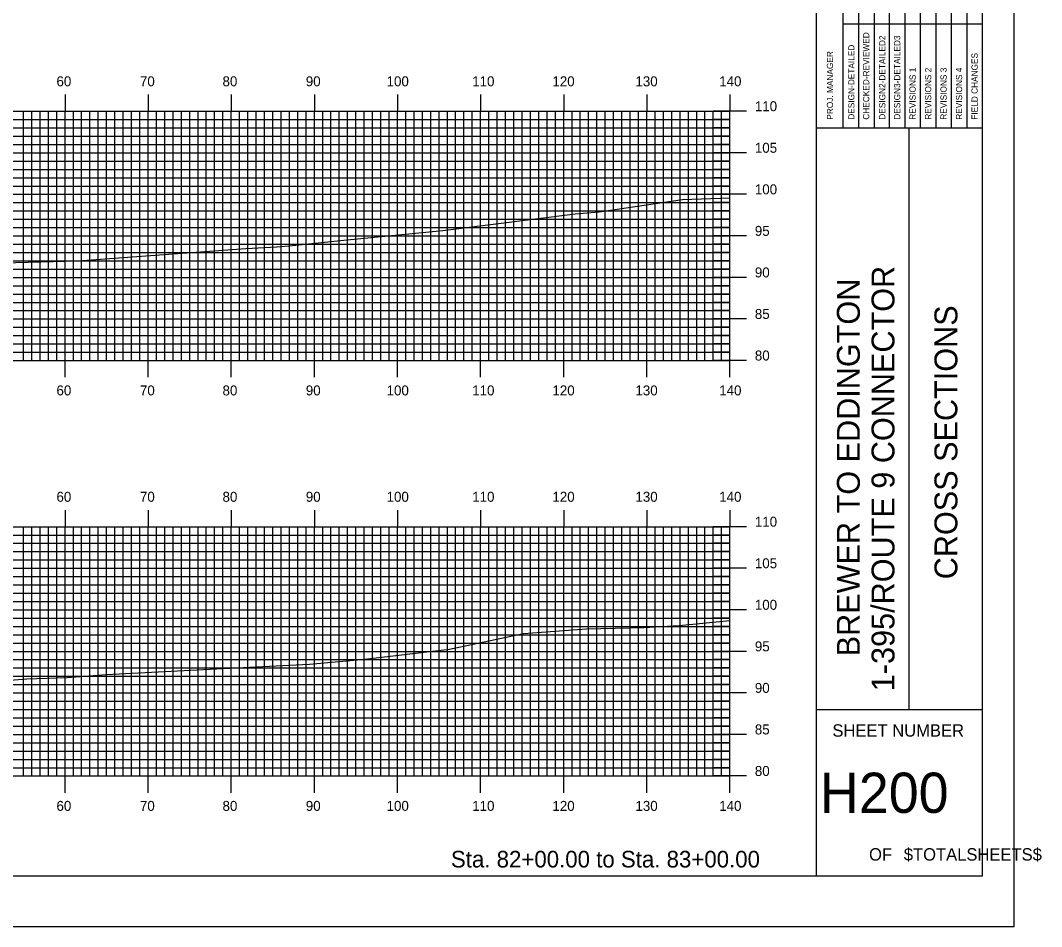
# Model space of a CAD drawing. Extents: x 1762972 to 1763315, y 442591 to 442811.
# Drawn here: x 1763191.9 to 1763314.8, y 442590.5 to 442699.6 of the extents above; entities that cross this region are included whole.
import ezdxf

# ---------------------------------------------------------------- set-up
doc = ezdxf.new("R2010")
doc.units = 0
for name, color, linetype in [('BORDER', 7, 'Continuous'), ('H_V ANNOTATION', 7, 'Continuous'), ('MAJOR', 7, 'Continuous'), ('MINOR', 7, 'Continuous'), ('PLOT BOUNDARY', 7, 'Continuous'), ('S_Roadway_Centerline', 7, 'Continuous')]:
    doc.layers.add(name, color=color, linetype=linetype)

msp = doc.modelspace()

# ---------------------------------------------------------------- linework, layer by layer
at = {"layer": 'BORDER'}
for p, q in [((1763287.69, 442596.67), (1763287.69, 442806.67)), ((1763287.69, 442686.67), (1763307.69, 442686.67)), ((1763298.87, 442616.67), (1763298.87, 442686.67)), ((1763287.69, 442616.67), (1763307.69, 442616.67))]:
    msp.add_line(p, q, dxfattribs=at)
msp.add_lwpolyline([(1762987.69, 442596.67), (1763307.69, 442596.67), (1763307.69, 442806.67), (1762987.69, 442806.67)], close=True, dxfattribs=at)
for points in [[(1763292.79, 442686.68), (1763292.79, 442721.67)], [(1763294.65, 442721.67), (1763294.65, 442686.68)], [(1763296.51, 442686.68), (1763296.51, 442721.67)], [(1763298.38, 442686.68), (1763298.38, 442721.67)], [(1763300.24, 442686.68), (1763300.24, 442721.67)], [(1763302.1, 442686.68), (1763302.1, 442721.67)], [(1763303.97, 442686.68), (1763303.97, 442721.67)], [(1763305.83, 442686.68), (1763305.83, 442721.67)], [(1763290.92, 442686.68), (1763290.92, 442720.26)], [(1763290.92, 442699.17), (1763307.69, 442699.17)]]:
    msp.add_lwpolyline(points, dxfattribs=at)
at = {"layer": 'MAJOR'}
for p, q in [((1763197.29, 442690.67), (1763197.29, 442688.67)), ((1763207.29, 442690.67), (1763207.29, 442688.67)), ((1763217.29, 442690.67), (1763217.29, 442688.67)), ((1763227.29, 442690.67), (1763227.29, 442688.67)), ((1763237.29, 442690.67), (1763237.29, 442688.67)), ((1763247.29, 442690.67), (1763247.29, 442688.67)), ((1763257.29, 442690.67), (1763257.29, 442688.67)), ((1763267.29, 442690.67), (1763267.29, 442688.67)), ((1763277.29, 442690.67), (1763277.29, 442688.67)), ((1762997.29, 442688.67), (1763277.29, 442688.67)), ((1762997.29, 442688.67), (1763277.29, 442688.67)), ((1763197.29, 442658.67), (1763197.29, 442688.67)), ((1763207.29, 442658.67), (1763207.29, 442688.67)), ((1763217.29, 442658.67), (1763217.29, 442688.67)), ((1763227.29, 442658.67), (1763227.29, 442688.67)), ((1763237.29, 442658.67), (1763237.29, 442688.67)), ((1763247.29, 442658.67), (1763247.29, 442688.67)), ((1763257.29, 442658.67), (1763257.29, 442688.67)), ((1763267.29, 442658.67), (1763267.29, 442688.67)), ((1763279.3, 442688.67), (1763275.29, 442688.67)), ((1763277.29, 442658.67), (1763277.29, 442688.67)), ((1763277.29, 442658.67), (1763277.29, 442688.67)), ((1762997.29, 442683.67), (1763277.29, 442683.67)), ((1763279.3, 442683.67), (1763275.29, 442683.67)), ((1762997.29, 442678.67), (1763277.29, 442678.67)), ((1763279.3, 442678.67), (1763275.29, 442678.67)), ((1762997.29, 442673.67), (1763277.29, 442673.67)), ((1763279.3, 442673.67), (1763275.29, 442673.67)), ((1762997.29, 442668.67), (1763277.29, 442668.67)), ((1763279.3, 442668.67), (1763275.29, 442668.67)), ((1762997.29, 442663.67), (1763277.29, 442663.67)), ((1763279.3, 442663.67), (1763275.29, 442663.67)), ((1762997.29, 442658.67), (1763277.29, 442658.67)), ((1762997.29, 442658.67), (1763277.29, 442658.67)), ((1763197.29, 442656.66), (1763197.29, 442658.67)), ((1763207.29, 442656.66), (1763207.29, 442658.67)), ((1763217.29, 442656.66), (1763217.29, 442658.67)), ((1763227.29, 442656.66), (1763227.29, 442658.67)), ((1763237.29, 442656.66), (1763237.29, 442658.67)), ((1763247.29, 442656.66), (1763247.29, 442658.67)), ((1763257.29, 442656.66), (1763257.29, 442658.67)), ((1763267.29, 442656.66), (1763267.29, 442658.67)), ((1763279.3, 442658.67), (1763275.29, 442658.67)), ((1763277.29, 442656.66), (1763277.29, 442658.67)), ((1763197.29, 442640.67), (1763197.29, 442638.67)), ((1763207.29, 442640.67), (1763207.29, 442638.67)), ((1763217.29, 442640.67), (1763217.29, 442638.67)), ((1763227.29, 442640.67), (1763227.29, 442638.67)), ((1763237.29, 442640.67), (1763237.29, 442638.67)), ((1763247.29, 442640.67), (1763247.29, 442638.67)), ((1763257.29, 442640.67), (1763257.29, 442638.67)), ((1763267.29, 442640.67), (1763267.29, 442638.67)), ((1763277.29, 442640.67), (1763277.29, 442638.67)), ((1762997.29, 442638.67), (1763277.29, 442638.67)), ((1762997.29, 442638.67), (1763277.29, 442638.67)), ((1763197.29, 442608.67), (1763197.29, 442638.67)), ((1763207.29, 442608.67), (1763207.29, 442638.67)), ((1763217.29, 442608.67), (1763217.29, 442638.67)), ((1763227.29, 442608.67), (1763227.29, 442638.67)), ((1763237.29, 442608.67), (1763237.29, 442638.67)), ((1763247.29, 442608.67), (1763247.29, 442638.67)), ((1763257.29, 442608.67), (1763257.29, 442638.67)), ((1763267.29, 442608.67), (1763267.29, 442638.67)), ((1763279.3, 442638.67), (1763275.29, 442638.67)), ((1763277.29, 442608.67), (1763277.29, 442638.67)), ((1763277.29, 442608.67), (1763277.29, 442638.67)), ((1762997.29, 442633.67), (1763277.29, 442633.67)), ((1763279.3, 442633.67), (1763275.29, 442633.67)), ((1762997.29, 442628.67), (1763277.29, 442628.67)), ((1763279.3, 442628.67), (1763275.29, 442628.67)), ((1762997.29, 442623.67), (1763277.29, 442623.67)), ((1763279.3, 442623.67), (1763275.29, 442623.67)), ((1762997.29, 442618.67), (1763277.29, 442618.67)), ((1763279.3, 442618.67), (1763275.29, 442618.67)), ((1762997.29, 442613.67), (1763277.29, 442613.67)), ((1763279.3, 442613.67), (1763275.29, 442613.67)), ((1762997.29, 442608.67), (1763277.29, 442608.67)), ((1762997.29, 442608.67), (1763277.29, 442608.67)), ((1763197.29, 442606.66), (1763197.29, 442608.67)), ((1763207.29, 442606.66), (1763207.29, 442608.67)), ((1763217.29, 442606.66), (1763217.29, 442608.67)), ((1763227.29, 442606.66), (1763227.29, 442608.67)), ((1763237.29, 442606.66), (1763237.29, 442608.67)), ((1763247.29, 442606.66), (1763247.29, 442608.67)), ((1763257.29, 442606.66), (1763257.29, 442608.67)), ((1763267.29, 442606.66), (1763267.29, 442608.67)), ((1763279.3, 442608.67), (1763275.29, 442608.67)), ((1763277.29, 442606.66), (1763277.29, 442608.67))]:
    msp.add_line(p, q, dxfattribs=at)
at = {"layer": 'MINOR'}
for p, q in [((1763192.29, 442658.67), (1763192.29, 442688.67)), ((1763193.29, 442658.67), (1763193.29, 442688.67)), ((1763194.29, 442658.67), (1763194.29, 442688.67)), ((1763195.29, 442658.67), (1763195.29, 442688.67)), ((1763196.29, 442658.67), (1763196.29, 442688.67)), ((1763198.29, 442658.67), (1763198.29, 442688.67)), ((1763199.29, 442658.67), (1763199.29, 442688.67)), ((1763200.29, 442658.67), (1763200.29, 442688.67)), ((1763201.29, 442658.67), (1763201.29, 442688.67)), ((1763202.29, 442658.67), (1763202.29, 442688.67)), ((1763203.29, 442658.67), (1763203.29, 442688.67)), ((1763204.29, 442658.67), (1763204.29, 442688.67)), ((1763205.29, 442658.67), (1763205.29, 442688.67)), ((1763206.29, 442658.67), (1763206.29, 442688.67)), ((1763208.29, 442658.67), (1763208.29, 442688.67)), ((1763209.29, 442658.67), (1763209.29, 442688.67)), ((1763210.29, 442658.67), (1763210.29, 442688.67)), ((1763211.29, 442658.67), (1763211.29, 442688.67)), ((1763212.29, 442658.67), (1763212.29, 442688.67)), ((1763213.29, 442658.67), (1763213.29, 442688.67)), ((1763214.29, 442658.67), (1763214.29, 442688.67)), ((1763215.29, 442658.67), (1763215.29, 442688.67)), ((1763216.29, 442658.67), (1763216.29, 442688.67)), ((1763218.29, 442658.67), (1763218.29, 442688.67)), ((1763219.29, 442658.67), (1763219.29, 442688.67)), ((1763220.29, 442658.67), (1763220.29, 442688.67)), ((1763221.29, 442658.67), (1763221.29, 442688.67)), ((1763222.29, 442658.67), (1763222.29, 442688.67)), ((1763223.29, 442658.67), (1763223.29, 442688.67)), ((1763224.29, 442658.67), (1763224.29, 442688.67)), ((1763225.29, 442658.67), (1763225.29, 442688.67)), ((1763226.29, 442658.67), (1763226.29, 442688.67)), ((1763228.29, 442658.67), (1763228.29, 442688.67)), ((1763229.29, 442658.67), (1763229.29, 442688.67)), ((1763230.29, 442658.67), (1763230.29, 442688.67)), ((1763231.29, 442658.67), (1763231.29, 442688.67)), ((1763232.29, 442658.67), (1763232.29, 442688.67)), ((1763233.29, 442658.67), (1763233.29, 442688.67)), ((1763234.29, 442658.67), (1763234.29, 442688.67)), ((1763235.29, 442658.67), (1763235.29, 442688.67)), ((1763236.29, 442658.67), (1763236.29, 442688.67)), ((1763238.29, 442658.67), (1763238.29, 442688.67)), ((1763239.29, 442658.67), (1763239.29, 442688.67)), ((1763240.29, 442658.67), (1763240.29, 442688.67)), ((1763241.29, 442658.67), (1763241.29, 442688.67)), ((1763242.29, 442658.67), (1763242.29, 442688.67)), ((1763243.29, 442658.67), (1763243.29, 442688.67)), ((1763244.29, 442658.67), (1763244.29, 442688.67)), ((1763245.29, 442658.67), (1763245.29, 442688.67)), ((1763246.29, 442658.67), (1763246.29, 442688.67)), ((1763248.29, 442658.67), (1763248.29, 442688.67)), ((1763249.29, 442658.67), (1763249.29, 442688.67)), ((1763250.29, 442658.67), (1763250.29, 442688.67)), ((1763251.29, 442658.67), (1763251.29, 442688.67)), ((1763252.29, 442658.67), (1763252.29, 442688.67)), ((1763253.29, 442658.67), (1763253.29, 442688.67)), ((1763254.29, 442658.67), (1763254.29, 442688.67)), ((1763255.29, 442658.67), (1763255.29, 442688.67)), ((1763256.29, 442658.67), (1763256.29, 442688.67)), ((1763258.29, 442658.67), (1763258.29, 442688.67)), ((1763259.29, 442658.67), (1763259.29, 442688.67)), ((1763260.29, 442658.67), (1763260.29, 442688.67)), ((1763261.29, 442658.67), (1763261.29, 442688.67)), ((1763262.29, 442658.67), (1763262.29, 442688.67)), ((1763263.29, 442658.67), (1763263.29, 442688.67)), ((1763264.29, 442658.67), (1763264.29, 442688.67)), ((1763265.29, 442658.67), (1763265.29, 442688.67)), ((1763266.29, 442658.67), (1763266.29, 442688.67)), ((1763268.29, 442658.67), (1763268.29, 442688.67)), ((1763269.29, 442658.67), (1763269.29, 442688.67)), ((1763270.29, 442658.67), (1763270.29, 442688.67)), ((1763271.29, 442658.67), (1763271.29, 442688.67)), ((1763272.29, 442658.67), (1763272.29, 442688.67)), ((1763273.29, 442658.67), (1763273.29, 442688.67)), ((1763274.29, 442658.67), (1763274.29, 442688.67)), ((1763275.29, 442658.67), (1763275.29, 442688.67)), ((1763276.29, 442658.67), (1763276.29, 442688.67)), ((1762997.29, 442687.67), (1763277.29, 442687.67)), ((1763277.29, 442687.67), (1763275.29, 442687.67)), ((1762997.29, 442686.67), (1763277.29, 442686.67)), ((1763277.29, 442686.67), (1763275.29, 442686.67)), ((1762997.29, 442685.67), (1763277.29, 442685.67)), ((1762997.29, 442684.67), (1763277.29, 442684.67)), ((1763277.29, 442685.67), (1763275.29, 442685.67)), ((1763277.29, 442684.67), (1763275.29, 442684.67)), ((1762997.29, 442682.67), (1763277.29, 442682.67)), ((1763277.29, 442682.67), (1763275.29, 442682.67)), ((1762997.29, 442681.67), (1763277.29, 442681.67)), ((1763277.29, 442681.67), (1763275.29, 442681.67)), ((1762997.29, 442680.67), (1763277.29, 442680.67)), ((1762997.29, 442679.67), (1763277.29, 442679.67)), ((1763277.29, 442680.67), (1763275.29, 442680.67)), ((1763277.29, 442679.67), (1763275.29, 442679.67)), ((1762997.29, 442677.67), (1763277.29, 442677.67)), ((1763277.29, 442677.67), (1763275.29, 442677.67)), ((1762997.29, 442676.67), (1763277.29, 442676.67)), ((1763277.29, 442676.67), (1763275.29, 442676.67)), ((1762997.29, 442675.67), (1763277.29, 442675.67)), ((1763277.29, 442675.67), (1763275.29, 442675.67)), ((1762997.29, 442674.67), (1763277.29, 442674.67)), ((1763277.29, 442674.67), (1763275.29, 442674.67)), ((1762997.29, 442672.67), (1763277.29, 442672.67)), ((1763277.29, 442672.67), (1763275.29, 442672.67)), ((1762997.29, 442671.67), (1763277.29, 442671.67)), ((1763277.29, 442671.67), (1763275.29, 442671.67)), ((1762997.29, 442670.67), (1763277.29, 442670.67)), ((1763277.29, 442670.67), (1763275.29, 442670.67)), ((1762997.29, 442669.67), (1763277.29, 442669.67)), ((1763277.29, 442669.67), (1763275.29, 442669.67)), ((1762997.29, 442667.67), (1763277.29, 442667.67)), ((1763277.29, 442667.67), (1763275.29, 442667.67)), ((1762997.29, 442666.67), (1763277.29, 442666.67)), ((1763277.29, 442666.67), (1763275.29, 442666.67)), ((1762997.29, 442665.67), (1763277.29, 442665.67)), ((1763277.29, 442665.67), (1763275.29, 442665.67)), ((1762997.29, 442664.67), (1763277.29, 442664.67)), ((1763277.29, 442664.67), (1763275.29, 442664.67)), ((1762997.29, 442662.67), (1763277.29, 442662.67)), ((1763277.29, 442662.67), (1763275.29, 442662.67)), ((1762997.29, 442661.67), (1763277.29, 442661.67)), ((1763277.29, 442661.67), (1763275.29, 442661.67)), ((1762997.29, 442660.67), (1763277.29, 442660.67)), ((1763277.29, 442660.67), (1763275.29, 442660.67)), ((1762997.29, 442659.67), (1763277.29, 442659.67)), ((1763277.29, 442659.67), (1763275.29, 442659.67)), ((1763192.29, 442608.67), (1763192.29, 442638.67)), ((1763193.29, 442608.67), (1763193.29, 442638.67)), ((1763194.29, 442608.67), (1763194.29, 442638.67)), ((1763195.29, 442608.67), (1763195.29, 442638.67)), ((1763196.29, 442608.67), (1763196.29, 442638.67)), ((1763198.29, 442608.67), (1763198.29, 442638.67)), ((1763199.29, 442608.67), (1763199.29, 442638.67)), ((1763200.29, 442608.67), (1763200.29, 442638.67)), ((1763201.29, 442608.67), (1763201.29, 442638.67)), ((1763202.29, 442608.67), (1763202.29, 442638.67)), ((1763203.29, 442608.67), (1763203.29, 442638.67)), ((1763204.29, 442608.67), (1763204.29, 442638.67)), ((1763205.29, 442608.67), (1763205.29, 442638.67)), ((1763206.29, 442608.67), (1763206.29, 442638.67)), ((1763208.29, 442608.67), (1763208.29, 442638.67)), ((1763209.29, 442608.67), (1763209.29, 442638.67)), ((1763210.29, 442608.67), (1763210.29, 442638.67)), ((1763211.29, 442608.67), (1763211.29, 442638.67)), ((1763212.29, 442608.67), (1763212.29, 442638.67)), ((1763213.29, 442608.67), (1763213.29, 442638.67)), ((1763214.29, 442608.67), (1763214.29, 442638.67)), ((1763215.29, 442608.67), (1763215.29, 442638.67)), ((1763216.29, 442608.67), (1763216.29, 442638.67)), ((1763218.29, 442608.67), (1763218.29, 442638.67)), ((1763219.29, 442608.67), (1763219.29, 442638.67)), ((1763220.29, 442608.67), (1763220.29, 442638.67)), ((1763221.29, 442608.67), (1763221.29, 442638.67)), ((1763222.29, 442608.67), (1763222.29, 442638.67)), ((1763223.29, 442608.67), (1763223.29, 442638.67)), ((1763224.29, 442608.67), (1763224.29, 442638.67)), ((1763225.29, 442608.67), (1763225.29, 442638.67)), ((1763226.29, 442608.67), (1763226.29, 442638.67)), ((1763228.29, 442608.67), (1763228.29, 442638.67)), ((1763229.29, 442608.67), (1763229.29, 442638.67)), ((1763230.29, 442608.67), (1763230.29, 442638.67)), ((1763231.29, 442608.67), (1763231.29, 442638.67)), ((1763232.29, 442608.67), (1763232.29, 442638.67)), ((1763233.29, 442608.67), (1763233.29, 442638.67)), ((1763234.29, 442608.67), (1763234.29, 442638.67)), ((1763235.29, 442608.67), (1763235.29, 442638.67)), ((1763236.29, 442608.67), (1763236.29, 442638.67)), ((1763238.29, 442608.67), (1763238.29, 442638.67)), ((1763239.29, 442608.67), (1763239.29, 442638.67)), ((1763240.29, 442608.67), (1763240.29, 442638.67)), ((1763241.29, 442608.67), (1763241.29, 442638.67)), ((1763242.29, 442608.67), (1763242.29, 442638.67)), ((1763243.29, 442608.67), (1763243.29, 442638.67)), ((1763244.29, 442608.67), (1763244.29, 442638.67)), ((1763245.29, 442608.67), (1763245.29, 442638.67)), ((1763246.29, 442608.67), (1763246.29, 442638.67)), ((1763248.29, 442608.67), (1763248.29, 442638.67)), ((1763249.29, 442608.67), (1763249.29, 442638.67)), ((1763250.29, 442608.67), (1763250.29, 442638.67)), ((1763251.29, 442608.67), (1763251.29, 442638.67)), ((1763252.29, 442608.67), (1763252.29, 442638.67)), ((1763253.29, 442608.67), (1763253.29, 442638.67)), ((1763254.29, 442608.67), (1763254.29, 442638.67)), ((1763255.29, 442608.67), (1763255.29, 442638.67)), ((1763256.29, 442608.67), (1763256.29, 442638.67)), ((1763258.29, 442608.67), (1763258.29, 442638.67)), ((1763259.29, 442608.67), (1763259.29, 442638.67)), ((1763260.29, 442608.67), (1763260.29, 442638.67)), ((1763261.29, 442608.67), (1763261.29, 442638.67)), ((1763262.29, 442608.67), (1763262.29, 442638.67)), ((1763263.29, 442608.67), (1763263.29, 442638.67)), ((1763264.29, 442608.67), (1763264.29, 442638.67)), ((1763265.29, 442608.67), (1763265.29, 442638.67)), ((1763266.29, 442608.67), (1763266.29, 442638.67)), ((1763268.29, 442608.67), (1763268.29, 442638.67)), ((1763269.29, 442608.67), (1763269.29, 442638.67)), ((1763270.29, 442608.67), (1763270.29, 442638.67)), ((1763271.29, 442608.67), (1763271.29, 442638.67)), ((1763272.29, 442608.67), (1763272.29, 442638.67)), ((1763273.29, 442608.67), (1763273.29, 442638.67)), ((1763274.29, 442608.67), (1763274.29, 442638.67)), ((1763275.29, 442608.67), (1763275.29, 442638.67)), ((1763276.29, 442608.67), (1763276.29, 442638.67)), ((1762997.29, 442637.67), (1763277.29, 442637.67)), ((1762997.29, 442636.67), (1763277.29, 442636.67)), ((1763277.29, 442637.67), (1763275.29, 442637.67)), ((1763277.29, 442636.67), (1763275.29, 442636.67)), ((1762997.29, 442635.67), (1763277.29, 442635.67)), ((1763277.29, 442635.67), (1763275.29, 442635.67)), ((1762997.29, 442634.67), (1763277.29, 442634.67)), ((1763277.29, 442634.67), (1763275.29, 442634.67)), ((1762997.29, 442632.67), (1763277.29, 442632.67)), ((1763277.29, 442632.67), (1763275.29, 442632.67)), ((1762997.29, 442631.67), (1763277.29, 442631.67)), ((1762997.29, 442630.67), (1763277.29, 442630.67)), ((1763277.29, 442631.67), (1763275.29, 442631.67)), ((1763277.29, 442630.67), (1763275.29, 442630.67)), ((1762997.29, 442629.67), (1763277.29, 442629.67)), ((1763277.29, 442629.67), (1763275.29, 442629.67)), ((1762997.29, 442627.67), (1763277.29, 442627.67)), ((1763277.29, 442627.67), (1763275.29, 442627.67)), ((1762997.29, 442626.67), (1763277.29, 442626.67)), ((1762997.29, 442625.67), (1763277.29, 442625.67)), ((1763277.29, 442626.67), (1763275.29, 442626.67)), ((1763277.29, 442625.67), (1763275.29, 442625.67)), ((1762997.29, 442624.67), (1763277.29, 442624.67)), ((1763277.29, 442624.67), (1763275.29, 442624.67)), ((1762997.29, 442622.67), (1763277.29, 442622.67)), ((1763277.29, 442622.67), (1763275.29, 442622.67)), ((1762997.29, 442621.67), (1763277.29, 442621.67)), ((1763277.29, 442621.67), (1763275.29, 442621.67)), ((1762997.29, 442620.67), (1763277.29, 442620.67)), ((1762997.29, 442619.67), (1763277.29, 442619.67)), ((1763277.29, 442620.67), (1763275.29, 442620.67)), ((1763277.29, 442619.67), (1763275.29, 442619.67)), ((1762997.29, 442617.67), (1763277.29, 442617.67)), ((1763277.29, 442617.67), (1763275.29, 442617.67)), ((1762997.29, 442616.67), (1763277.29, 442616.67)), ((1763277.29, 442616.67), (1763275.29, 442616.67)), ((1762997.29, 442615.67), (1763277.29, 442615.67)), ((1762997.29, 442614.67), (1763277.29, 442614.67)), ((1763277.29, 442615.67), (1763275.29, 442615.67)), ((1763277.29, 442614.67), (1763275.29, 442614.67)), ((1762997.29, 442612.67), (1763277.29, 442612.67)), ((1763277.29, 442612.67), (1763275.29, 442612.67)), ((1762997.29, 442611.67), (1763277.29, 442611.67)), ((1763277.29, 442611.67), (1763275.29, 442611.67)), ((1762997.29, 442610.67), (1763277.29, 442610.67)), ((1762997.29, 442609.67), (1763277.29, 442609.67)), ((1763277.29, 442610.67), (1763275.29, 442610.67)), ((1763277.29, 442609.67), (1763275.29, 442609.67))]:
    msp.add_line(p, q, dxfattribs=at)
at = {"layer": 'PLOT BOUNDARY'}
msp.add_lwpolyline([(1762971.51, 442590.55), (1763311.51, 442590.55), (1763311.51, 442810.55), (1762971.51, 442810.55)], close=True, dxfattribs=at)
at = {"layer": 'S_Roadway_Centerline'}
for points in [[(1763188.37, 442670.4), (1763198.83, 442670.65), (1763219.06, 442672.15), (1763222.79, 442672.35), (1763224.64, 442672.51), (1763230.83, 442673.15), (1763242.75, 442674.31), (1763253.91, 442675.7), (1763258.66, 442676.34), (1763261.54, 442676.55), (1763271.58, 442678.06), (1763277.29, 442678.23)], [(1763184.04, 442619.67), (1763192.69, 442620.38), (1763197.53, 442620.54), (1763202.22, 442620.9), (1763215.51, 442621.56), (1763226.72, 442622.14), (1763233.36, 442622.73), (1763243.55, 442623.95), (1763252.44, 442625.8), (1763260.03, 442626.36), (1763266.93, 442626.52), (1763271.18, 442626.76), (1763277.29, 442627.39)]]:
    msp.add_lwpolyline(points, dxfattribs=at)

# ---------------------------------------------------------------- texts
at = {"layer": 'BORDER'}
for s, height, p in [('CHECKED-REVIEWED', 0.7455, (1763294.05, 442687.65)), ('DESIGN2-DETAILED2', 0.7455, (1763295.99, 442687.65)), ('DESIGN3-DETAILED3', 0.7455, (1763297.78, 442687.65)), ('PROJ. MANAGER', 0.7455, (1763289.7, 442687.65)), ('DESIGN-DETAILED', 0.7455, (1763292.27, 442687.65)), ('FIELD CHANGES', 0.7455, (1763307.1, 442687.65)), ('REVISIONS 1', 0.7455, (1763299.64, 442687.65)), ('REVISIONS 2', 0.7455, (1763301.51, 442687.65)), ('REVISIONS 3', 0.7455, (1763303.37, 442687.65)), ('REVISIONS 4', 0.7455, (1763305.23, 442687.65)), ('1-395/ROUTE 9 CONNECTOR', 2.7557, (1763297.09, 442618.87)), ('BREWER TO EDDINGTON', 2.7557, (1763292.92, 442623.07)), ('CROSS SECTIONS', 2.7557, (1763304.66, 442632.34))]:
    msp.add_text(s, height=height, rotation=90, dxfattribs=at).set_placement(p)
for s, height, p in [('SHEET NUMBER', 1.4905, (1763289.62, 442613.4)), ('H200', 4.839, (1763288.13, 442604.23)), ('OF', 1.491, (1763294.03, 442598.49)), ('$TOTALSHEETS$', 1.4905, (1763298.21, 442598.49))]:
    msp.add_text(s, height=height, dxfattribs=at).set_placement(p)
at = {"layer": 'H_V ANNOTATION'}
for s, height, p in [('60', 1.2, (1763196.26, 442691.67)), ('70', 1.2, (1763206.3, 442691.67)), ('80', 1.2, (1763216.24, 442691.67)), ('90', 1.2, (1763226.26, 442691.67)), ('100', 1.2, (1763235.98, 442691.67)), ('110', 1.2, (1763246.28, 442691.67)), ('120', 1.2, (1763255.93, 442691.67)), ('130', 1.2, (1763265.92, 442691.67)), ('140', 1.2, (1763276, 442691.67)), ('110', 1.2, (1763280.29, 442688.67)), ('105', 1.2, (1763280.29, 442683.67)), ('100', 1.2, (1763280.29, 442678.67)), ('95', 1.2, (1763280.29, 442673.67)), ('90', 1.2, (1763280.29, 442668.67)), ('85', 1.2, (1763280.29, 442663.67)), ('80', 1.2, (1763280.29, 442658.67)), ('60', 1.2, (1763196.26, 442654.47)), ('70', 1.2, (1763206.3, 442654.47)), ('80', 1.2, (1763216.24, 442654.47)), ('90', 1.2, (1763226.26, 442654.47)), ('100', 1.2, (1763235.98, 442654.47)), ('110', 1.2, (1763246.28, 442654.47)), ('120', 1.2, (1763255.93, 442654.47)), ('130', 1.2, (1763265.92, 442654.47)), ('140', 1.2, (1763276, 442654.47)), ('60', 1.2, (1763196.26, 442641.67)), ('70', 1.2, (1763206.3, 442641.67)), ('80', 1.2, (1763216.24, 442641.67)), ('90', 1.2, (1763226.26, 442641.67)), ('100', 1.2, (1763235.98, 442641.67)), ('110', 1.2, (1763246.28, 442641.67)), ('120', 1.2, (1763255.93, 442641.67)), ('130', 1.2, (1763265.92, 442641.67)), ('140', 1.2, (1763276, 442641.67)), ('110', 1.2, (1763280.29, 442638.67)), ('105', 1.2, (1763280.29, 442633.67)), ('100', 1.2, (1763280.29, 442628.67)), ('95', 1.2, (1763280.29, 442623.67)), ('90', 1.2, (1763280.29, 442618.67)), ('85', 1.2, (1763280.29, 442613.67)), ('80', 1.2, (1763280.29, 442608.67)), ('60', 1.2, (1763196.26, 442604.47)), ('70', 1.2, (1763206.3, 442604.47)), ('80', 1.2, (1763216.24, 442604.47)), ('90', 1.2, (1763226.26, 442604.47)), ('100', 1.2, (1763235.98, 442604.47)), ('110', 1.2, (1763246.28, 442604.47)), ('120', 1.2, (1763255.93, 442604.47)), ('130', 1.2, (1763265.92, 442604.47)), ('140', 1.2, (1763276, 442604.47)), ('Sta. 82+00.00 to Sta. 83+00.00', 2.0004, (1763243.72, 442597.66))]:
    msp.add_text(s, height=height, dxfattribs=at).set_placement(p)

doc.saveas('drawing.dxf')
